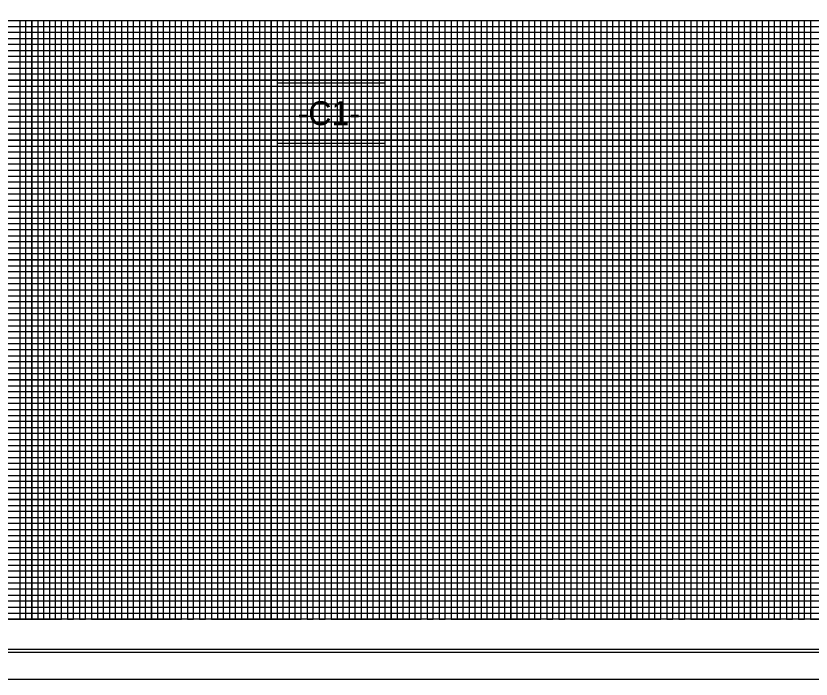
# Model space of a CAD drawing. Extents: x 1648862 to 1650889, y 802691 to 803791.
# Drawn here: x 1649516 to 1650180, y 802691 to 803245 of the extents above; entities that cross this region are included whole.
import ezdxf

# ---------------------------------------------------------------- set-up
doc = ezdxf.new("R2010")
doc.units = 0
for name, color, linetype in [('Exist Vertical Profile Horizontal Axis Label Major', 7, 'Continuous'), ('Prop Grid Mask', 7, 'Continuous'), ('Sheet Cutting Line CELL', 7, 'Continuous'), ('Sheet DOT Grid CELL', 7, 'Continuous'), ('Sheet Layout Profile Border Port 2', 7, 'Continuous'), ('Sheet Plot Border Inside CELL', 7, 'Continuous'), ('Sheet Plot Border Outside CELL', 7, 'Continuous'), ('Sheet Profile CELL', 7, 'Continuous'), ('Sheet Profile Grid Major CELL', 7, 'Continuous'), ('Sheet Profile Grid Middle CELL', 7, 'Continuous'), ('Sheet Profile Grid Minor CELL', 7, 'Continuous')]:
    doc.layers.add(name, color=color, linetype=linetype)

msp = doc.modelspace()

# ---------------------------------------------------------------- linework, layer by layer
at = {"layer": 'Prop Grid Mask'}
msp.add_lwpolyline([(1649734.28, 803188.52), (1649734.28, 803138.52), (1649824.28, 803138.52), (1649824.28, 803188.52)], close=True, dxfattribs=at)
at = {"layer": 'Sheet Cutting Line CELL'}
msp.add_line((1648862.28, 802691.02), (1650546.28, 802691.02), dxfattribs=at)
at = {"layer": 'Sheet DOT Grid CELL'}
for p, q in [((1649029.28, 803241.02), (1650529.17, 803241.02)), ((1649529.28, 803241.02), (1649529.28, 802741.02)), ((1649579.28, 803241.02), (1649579.28, 802741.02)), ((1649629.28, 803241.02), (1649629.28, 802741.02)), ((1649679.28, 803241.02), (1649679.28, 802741.02)), ((1649729.28, 803241.02), (1649729.28, 802741.02)), ((1649779.28, 803241.02), (1649779.28, 802741.02)), ((1649829.28, 803241.02), (1649829.28, 802741.02)), ((1649879.28, 803241.02), (1649879.28, 802741.02)), ((1649929.28, 803241.02), (1649929.28, 802741.02)), ((1649979.28, 803241.02), (1649979.28, 802741.02)), ((1650029.28, 803241.02), (1650029.28, 802741.02)), ((1650079.28, 803241.02), (1650079.28, 802741.02)), ((1650129.28, 803241.02), (1650129.28, 802741.02)), ((1650179.28, 803241.02), (1650179.28, 802741.02)), ((1649029.28, 803191.02), (1650529.17, 803191.02)), ((1649029.28, 803141.02), (1650529.17, 803141.02)), ((1649029.28, 803091.02), (1650529.17, 803091.02)), ((1649029.28, 803041.02), (1650529.17, 803041.02)), ((1649029.28, 802991.02), (1650529.17, 802991.02)), ((1649029.28, 802941.02), (1650529.17, 802941.02)), ((1649029.28, 802891.02), (1650529.17, 802891.02)), ((1649029.28, 802841.02), (1650529.17, 802841.02)), ((1649029.28, 802791.02), (1650529.17, 802791.02))]:
    msp.add_line(p, q, dxfattribs=at)
at = {"layer": 'Sheet Layout Profile Border Port 2'}
msp.add_lwpolyline([(1649079.28, 803241.02), (1650479.28, 803241.02), (1650479.28, 802741.02), (1649079.28, 802741.02)], close=True, dxfattribs=at)
at = {"layer": 'Sheet Plot Border Inside CELL'}
msp.add_lwpolyline([(1648875.28, 802713.47), (1650541.78, 802713.47), (1650541.78, 803768.57), (1648875.28, 803768.57)], close=True, dxfattribs=at)
at = {"layer": 'Sheet Plot Border Outside CELL'}
msp.add_lwpolyline([(1648862.28, 802691.02), (1650546.28, 802691.02), (1650546.28, 803791.02), (1648862.28, 803791.02)], close=True, dxfattribs=at)
at = {"layer": 'Sheet Profile CELL'}
for p, q in [((1649029.28, 803241.02), (1650529.28, 803241.02)), ((1650529.28, 802741.02), (1649029.28, 802741.02)), ((1649029.28, 802716.02), (1650529.28, 802716.02))]:
    msp.add_line(p, q, dxfattribs=at)
msp.add_lwpolyline([(1650529.28, 803766.02), (1649029.28, 803766.02), (1649029.28, 802716.02), (1650529.28, 802716.02)], close=True, dxfattribs=at)
at = {"layer": 'Sheet Profile Grid Major CELL'}
for p, q in [((1649529.28, 803241.02), (1649579.28, 803241.02)), ((1649629.28, 803241.02), (1649679.28, 803241.02)), ((1649729.28, 803241.02), (1649779.28, 803241.02)), ((1649829.28, 803241.02), (1649879.28, 803241.02)), ((1649929.28, 803241.02), (1649979.28, 803241.02)), ((1650029.28, 803241.02), (1650079.28, 803241.02)), ((1650129.28, 803241.02), (1650179.28, 803241.02))]:
    msp.add_line(p, q, dxfattribs=at)
for points in [[(1649479.28, 802741.02), (1649529.28, 802741.02), (1649529.28, 803241.02), (1649579.28, 803241.02), (1649579.28, 802741.02), (1649629.28, 802741.02), (1649629.28, 803241.02), (1649679.28, 803241.02), (1649679.28, 802741.02), (1649729.28, 802741.02), (1649729.28, 803241.02), (1649779.28, 803241.02), (1649779.28, 802741.02), (1649829.28, 802741.02), (1649829.28, 803241.02), (1649879.28, 803241.02), (1649879.28, 802741.02), (1649929.28, 802741.02), (1649929.28, 803241.02), (1649979.28, 803241.02), (1649979.28, 802741.02), (1650029.28, 802741.02), (1650029.28, 803241.02), (1650079.28, 803241.02), (1650079.28, 802741.02), (1650129.28, 802741.02), (1650129.28, 803241.02), (1650179.28, 803241.02), (1650179.28, 802741.02), (1650229.28, 802741.02)], [(1650529.28, 803191.02), (1649029.28, 803191.02)], [(1650529.28, 803141.02), (1649029.28, 803141.02), (1649029.28, 803091.02), (1650529.28, 803091.02)], [(1650529.28, 803041.02), (1649029.28, 803041.02), (1649029.28, 802991.02), (1650529.28, 802991.02)], [(1650529.28, 802941.02), (1649029.28, 802941.02), (1649029.28, 802891.02), (1650529.28, 802891.02)], [(1650529.28, 802841.02), (1649029.28, 802841.02), (1649029.28, 802841.02), (1649029.28, 802791.02), (1650529.28, 802791.02)], [(1650529.28, 802741.02), (1649029.28, 802741.02)]]:
    msp.add_lwpolyline(points, dxfattribs=at)
at = {"layer": 'Sheet Profile Grid Middle CELL'}
for points in [[(1649504.28, 802741.02), (1649554.28, 802741.02), (1649554.28, 803241.02), (1649604.28, 803241.02), (1649604.28, 802741.02), (1649654.28, 802741.02), (1649654.28, 802741.02), (1649654.28, 803241.02), (1649704.28, 803241.02), (1649704.28, 802741.02), (1649754.28, 802741.02), (1649754.28, 803241.02), (1649804.28, 803241.02), (1649804.28, 802741.02), (1649854.28, 802741.02), (1649854.28, 803241.02), (1649904.28, 803241.02), (1649904.28, 802741.02), (1649954.28, 802741.02), (1649954.28, 803241.02), (1650004.28, 803241.02), (1650004.28, 802741.02), (1650054.28, 802741.02), (1650054.28, 803241.02), (1650104.28, 803241.02), (1650104.28, 802741.02), (1650154.28, 802741.02), (1650154.28, 803241.02), (1650204.28, 803241.02)], [(1649029.28, 803216.02), (1650529.28, 803216.02)], [(1650529.28, 803166.02), (1649029.28, 803166.02), (1649029.28, 803116.02), (1650529.28, 803116.02)], [(1650529.28, 803066.02), (1649029.28, 803066.02), (1649029.28, 803016.02), (1650529.28, 803016.02)], [(1650529.28, 802966.02), (1649029.28, 802966.02), (1649029.28, 802916.02), (1650529.28, 802916.02)], [(1650529.28, 802866.02), (1649029.28, 802866.02), (1649029.28, 802816.02), (1650529.28, 802816.02)], [(1650529.28, 802766.02), (1649029.28, 802766.02)]]:
    msp.add_lwpolyline(points, dxfattribs=at)
at = {"layer": 'Sheet Profile Grid Minor CELL'}
for p, q in [((1649079.28, 803236.02), (1650479.28, 803236.02)), ((1650479.28, 803231.02), (1649079.28, 803231.02)), ((1649079.28, 803226.02), (1650479.28, 803226.02)), ((1650479.28, 803221.02), (1649079.28, 803221.02)), ((1649079.28, 803211.02), (1650479.28, 803211.02)), ((1650479.28, 803206.02), (1649079.28, 803206.02)), ((1649079.28, 803201.02), (1650479.28, 803201.02)), ((1650479.28, 803196.02), (1649079.28, 803196.02)), ((1649079.28, 803186.02), (1650479.28, 803186.02)), ((1650479.28, 803181.02), (1649079.28, 803181.02)), ((1649079.28, 803176.02), (1650479.28, 803176.02)), ((1650479.28, 803171.02), (1649079.28, 803171.02)), ((1649079.28, 803161.02), (1650479.28, 803161.02)), ((1650479.28, 803156.02), (1649079.28, 803156.02)), ((1649079.28, 803151.02), (1650479.28, 803151.02)), ((1650479.28, 803146.02), (1649079.28, 803146.02)), ((1649079.28, 803136.02), (1650479.28, 803136.02)), ((1650479.28, 803131.02), (1649079.28, 803131.02)), ((1649079.28, 803126.02), (1650479.28, 803126.02)), ((1650479.28, 803121.02), (1649079.28, 803121.02)), ((1649079.28, 803111.02), (1650479.28, 803111.02)), ((1650479.28, 803106.02), (1649079.28, 803106.02)), ((1649079.28, 803101.02), (1650479.28, 803101.02)), ((1650479.28, 803096.02), (1649079.28, 803096.02)), ((1649079.28, 803086.02), (1650479.28, 803086.02)), ((1650479.28, 803081.02), (1649079.28, 803081.02)), ((1649079.28, 803076.02), (1650479.28, 803076.02)), ((1650479.28, 803071.02), (1649079.28, 803071.02)), ((1649079.28, 803061.02), (1650479.28, 803061.02)), ((1650479.28, 803056.02), (1649079.28, 803056.02)), ((1649079.28, 803051.02), (1650479.28, 803051.02)), ((1650479.28, 803046.02), (1649079.28, 803046.17)), ((1649079.28, 803036.02), (1650479.28, 803036.02)), ((1650479.28, 803031.02), (1649079.28, 803031.02)), ((1649079.28, 803026.02), (1650479.28, 803026.02)), ((1650479.28, 803021.02), (1649079.28, 803021.02)), ((1649079.28, 803011.02), (1650479.28, 803011.02)), ((1650479.28, 803006.02), (1649079.28, 803006.02)), ((1649079.28, 803001.02), (1650479.28, 803001.02)), ((1650479.28, 802996.02), (1649079.28, 802996.02)), ((1649079.28, 802986.02), (1650479.28, 802986.02)), ((1650479.28, 802981.02), (1649079.28, 802981.02)), ((1649079.28, 802976.02), (1650479.28, 802976.02)), ((1650479.28, 802971.02), (1649079.28, 802971.02)), ((1649079.28, 802961.02), (1650479.28, 802961.02)), ((1650479.28, 802956.02), (1649079.28, 802956.02)), ((1649079.28, 802951.02), (1650479.28, 802951.02)), ((1650479.28, 802946.02), (1649079.28, 802946.02)), ((1649079.28, 802936.02), (1650479.28, 802936.02)), ((1650479.28, 802931.02), (1649079.28, 802931.02)), ((1649079.28, 802926.02), (1650479.28, 802926.02)), ((1650479.28, 802921.02), (1649079.28, 802921.02)), ((1649079.28, 802911.02), (1650479.28, 802911.02)), ((1650479.28, 802906.02), (1649079.28, 802906.02)), ((1649079.28, 802901.02), (1650479.28, 802901.02)), ((1650479.28, 802896.02), (1649079.28, 802896.02)), ((1649079.28, 802886.02), (1650479.28, 802886.02)), ((1650479.28, 802881.02), (1649079.28, 802881.02)), ((1649079.28, 802876.02), (1650479.28, 802876.02)), ((1650479.28, 802871.02), (1649079.28, 802871.02)), ((1649079.28, 802861.02), (1650479.28, 802861.02)), ((1650479.28, 802856.02), (1649079.28, 802856.02)), ((1649079.28, 802851.02), (1650479.28, 802851.02)), ((1650479.28, 802846.02), (1649079.28, 802846.02)), ((1649079.28, 802836.02), (1650479.28, 802836.02)), ((1650479.28, 802831.02), (1649079.28, 802831.02)), ((1649079.28, 802826.02), (1650479.28, 802826.02)), ((1650479.28, 802821.02), (1649079.28, 802821.02)), ((1649079.28, 802811.02), (1650479.28, 802811.02)), ((1650479.28, 802806.02), (1649079.28, 802806.02)), ((1649079.28, 802801.02), (1650479.28, 802801.02)), ((1650479.28, 802796.02), (1649079.28, 802796.02)), ((1649079.28, 802786.02), (1650479.28, 802786.02)), ((1650479.28, 802781.02), (1649079.28, 802781.02)), ((1649079.28, 802776.02), (1650479.28, 802776.02)), ((1650479.28, 802771.02), (1649079.28, 802771.02)), ((1649079.28, 802761.02), (1650479.28, 802761.02)), ((1650479.28, 802756.02), (1649079.28, 802756.02)), ((1649079.28, 802751.02), (1650479.28, 802751.02)), ((1649079.28, 802746.02), (1650479.28, 802746.02))]:
    msp.add_line(p, q, dxfattribs=at)
for points in [[(1649514.28, 803241.02), (1649519.28, 803241.02), (1649519.28, 802741.02), (1649524.28, 802741.02), (1649524.28, 803241.02), (1649534.28, 803241.02), (1649534.28, 802741.02), (1649539.28, 802741.02), (1649539.28, 803241.02), (1649544.28, 803241.02), (1649544.28, 802741.02), (1649549.28, 802741.02), (1649549.28, 803241.02), (1649559.28, 803241.02), (1649559.28, 802741.02), (1649564.28, 802741.02), (1649564.28, 803241.02), (1649569.28, 803241.02), (1649569.28, 802741.02), (1649574.28, 802741.02), (1649574.28, 803241.02), (1649584.28, 803241.02), (1649584.28, 802741.02), (1649589.28, 802741.02), (1649589.28, 803241.02), (1649594.28, 803241.02), (1649594.28, 802741.02), (1649599.28, 802741.02), (1649599.28, 803241.02), (1649609.28, 803241.02)], [(1649609.28, 803241.02), (1649609.28, 802741.02), (1649614.28, 802741.02), (1649614.28, 803241.02), (1649619.28, 803241.02), (1649619.28, 802741.02), (1649624.28, 802741.02), (1649624.28, 803241.02), (1649634.28, 803241.02), (1649634.28, 802741.02), (1649639.28, 802741.02), (1649639.28, 803241.02), (1649644.28, 803241.02), (1649644.28, 802741.02), (1649649.28, 802741.02), (1649649.28, 803241.02), (1649659.28, 803241.02), (1649659.28, 802741.02), (1649664.28, 802741.02), (1649664.28, 803241.02), (1649669.28, 803241.02), (1649669.28, 802741.02), (1649674.28, 802741.02), (1649674.28, 803241.02), (1649684.28, 803241.02), (1649684.28, 802741.02), (1649689.28, 802741.02), (1649689.28, 803241.02), (1649694.28, 803241.02), (1649694.28, 802741.02), (1649699.28, 802741.02), (1649699.28, 803241.02), (1649709.28, 803241.02), (1649709.28, 802741.02), (1649714.28, 802741.02), (1649714.28, 803241.02), (1649719.28, 803241.02), (1649719.28, 802741.02), (1649724.28, 802741.02), (1649724.28, 803241.02), (1649734.28, 803241.02), (1649734.28, 802741.02), (1649734.28, 802741.02), (1649739.28, 802741.02), (1649739.28, 803241.02), (1649744.28, 803241.02), (1649744.28, 802741.02), (1649749.28, 802741.02), (1649749.28, 803241.02), (1649759.28, 803241.02), (1649759.28, 802741.02), (1649764.28, 802741.02), (1649764.28, 803241.02), (1649769.28, 803241.02), (1649769.28, 802741.02), (1649774.28, 802741.02), (1649774.28, 803241.02), (1649784.28, 803241.02), (1649784.28, 802741.02), (1649789.28, 802741.02), (1649789.28, 803241.02), (1649794.28, 803241.02), (1649794.28, 802741.02), (1649799.28, 802741.02), (1649799.28, 803241.02), (1649809.28, 803241.02), (1649809.28, 802741.02), (1649814.28, 802741.02), (1649814.28, 803241.02), (1649819.28, 803241.02), (1649819.28, 802741.02), (1649824.28, 802741.02), (1649824.28, 803241.02), (1649834.28, 803241.02), (1649834.28, 802741.02), (1649839.28, 802741.02), (1649839.28, 803241.02), (1649844.28, 803241.02), (1649844.28, 802741.02), (1649849.28, 802741.02), (1649849.28, 803241.02), (1649859.28, 803241.02), (1649859.28, 802741.02), (1649864.28, 802741.02), (1649864.28, 803241.02), (1649869.28, 803241.02), (1649869.28, 802741.02), (1649874.28, 802741.02), (1649874.28, 803241.02), (1649884.28, 803241.02), (1649884.28, 802741.02), (1649888.98, 802741.57), (1649889.28, 802741.02), (1649889.28, 803241.02), (1649894.28, 803241.02), (1649894.28, 802741.02), (1649899.28, 802741.02), (1649899.28, 803241.02), (1649909.28, 803241.02), (1649909.28, 802741.02), (1649914.28, 802741.02)], [(1649914.28, 802741.02), (1649914.28, 803241.02), (1649919.28, 803241.02), (1649919.28, 802741.02), (1649924.28, 802741.02), (1649924.28, 803241.02), (1649934.28, 803241.02), (1649934.28, 802741.02), (1649939.28, 802741.02), (1649939.28, 803241.02), (1649944.28, 803241.02), (1649944.28, 802741.02), (1649949.28, 802741.02), (1649949.28, 803241.02), (1649959.28, 803241.02), (1649959.28, 802741.02), (1649964.28, 802741.02), (1649964.28, 803241.02), (1649969.28, 803241.02), (1649969.28, 802741.02), (1649974.28, 802741.02), (1649974.28, 803241.02), (1649984.28, 803241.02), (1649984.28, 802741.02), (1649989.28, 802741.02), (1649989.28, 803241.02), (1649994.28, 803241.02), (1649994.28, 802741.02), (1649999.28, 802741.02), (1649999.28, 803241.02), (1650009.28, 803241.02), (1650009.28, 802741.02), (1650014.28, 802741.02), (1650014.28, 803241.02), (1650019.28, 803241.02), (1650019.28, 802741.02), (1650024.28, 802741.02), (1650024.28, 803241.02), (1650034.28, 803241.02), (1650034.28, 802741.02), (1650039.28, 802741.02), (1650039.28, 803241.02), (1650044.28, 803241.02), (1650044.28, 802741.02), (1650049.28, 802741.02), (1650049.28, 803241.02), (1650059.28, 803241.02), (1650059.28, 802741.02), (1650064.28, 802741.02), (1650064.28, 803241.02), (1650069.28, 803241.02), (1650069.28, 802741.02), (1650074.28, 802741.02), (1650074.28, 803241.02), (1650084.28, 803241.02), (1650084.28, 802741.02), (1650089.28, 802741.02), (1650089.28, 803241.02), (1650094.28, 803241.02), (1650094.28, 802741.02), (1650099.28, 802741.02), (1650099.28, 803241.02), (1650109.28, 803241.02), (1650109.28, 802741.02), (1650114.28, 802741.02), (1650114.28, 803241.02), (1650119.28, 803241.02), (1650119.28, 802741.02), (1650124.28, 802741.02), (1650124.28, 803241.02), (1650134.28, 803241.02), (1650134.28, 802741.02), (1650139.28, 802741.02), (1650139.28, 803241.02), (1650144.28, 803241.02), (1650144.28, 802741.02), (1650149.28, 802741.02), (1650149.28, 803241.02), (1650159.28, 803241.02), (1650159.28, 802741.02), (1650164.28, 802741.02), (1650164.28, 803241.02), (1650169.28, 803241.02), (1650169.28, 802741.02), (1650174.28, 802741.02), (1650174.28, 803241.02), (1650184.28, 803241.02)]]:
    msp.add_lwpolyline(points, dxfattribs=at)

# ---------------------------------------------------------------- texts
at = {"layer": 'Exist Vertical Profile Horizontal Axis Label Major'}
msp.add_text('-C1-', height=20, dxfattribs=at).set_placement((1649751.28, 803153.52))

doc.saveas('drawing.dxf')
